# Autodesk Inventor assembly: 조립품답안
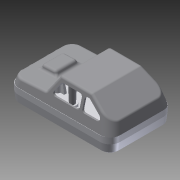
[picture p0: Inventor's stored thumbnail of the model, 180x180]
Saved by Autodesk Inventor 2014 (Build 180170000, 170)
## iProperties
Created: 2015-05
Part Number: 조립품답안
Document SubType Name: Assembly
Designer: Administrator
Author: Administrator
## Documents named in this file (7)
- C:\Users\Administrator\Desktop\450508V1057\조립품답안.iam
- C:\Users\Administrator\Desktop\450508V1057\M2x4.ipt
- C:\Users\Administrator\Desktop\450508V1057\M4x10.ipt
- C:\Users\Administrator\Desktop\450508V1057\바퀴.ipt
- C:\Users\Administrator\Desktop\450508V1057\바퀴고정부.ipt
- C:\Users\Administrator\Desktop\450508V1057\본체답안.ipt
- C:\Users\Administrator\Desktop\450508V1057\커버.ipt
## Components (20 placed, 2 different names)
1. M2x4:1
2. M4x10:1
3. M4x10:2
4. M4x10:3
5. M4x10:4
6. M2x4:2
7. M2x4:3
8. M2x4:4
9. M2x4:5
10. M2x4:6
11. M2x4:7
12. M2x4:8
13. M2x4:9
14. M2x4:10
15. M2x4:11
16. M2x4:12
17. M2x4:13
18. M2x4:14
19. M2x4:15
20. M2x4:16
